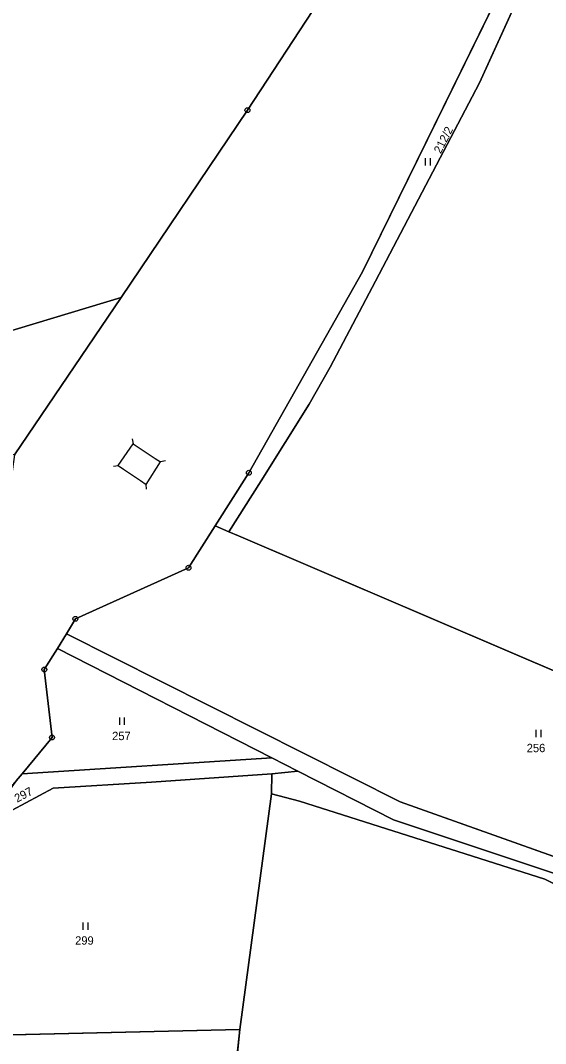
# Model space of a CAD drawing. Extents: x -689422 to -685210, y -987725 to -982160.
# Drawn here: x -686432.7 to -686325.7, y -987064.7 to -986856.4 of the extents above; entities that cross this region are included whole.
import ezdxf

# ---------------------------------------------------------------- set-up
doc = ezdxf.new("R2010")
doc.units = 0
for name, color, linetype in [('KN_Hranice_parcel', 7, 'Continuous'), ('KN_Hranice_parcel_vnitrni_kresba', 7, 'Continuous'), ('KN_Parcelni cisla', 7, 'Continuous'), ('KN_Polygon parcely', 7, 'Continuous'), ('KN_POZEMKY_ORNA PUDA', 7, 'Continuous'), ('KN_POZEMKY_OSTATNI PLOCHA', 7, 'Continuous'), ('KN_POZEMKY_TTP', 7, 'Continuous'), ('KN_POZEMKY_VODNI_PLOCHA', 7, 'Continuous'), ('KN_VYUZITI_11_vodni plocha_zamokrena plocha', 7, 'Continuous'), ('KN_VYUZITI_14_ostatni plocha_dráha', 7, 'Continuous'), ('KN_VYUZITI_17_ostatni plocha_ostatni komunikace', 7, 'Continuous'), ('KN_Značky bodu BP', 7, 'Continuous'), ('KN_Značky kultur', 7, 'Continuous')]:
    doc.layers.add(name, color=color, linetype=linetype)

msp = doc.modelspace()

# ---------------------------------------------------------------- linework, layer by layer
at = {"layer": 'KN_Hranice_parcel'}
for p, q in [((-686386.41, -986874.65), (-686371.81, -986852.38)), ((-686412.17, -986912.77), (-686386.41, -986874.65)), ((-686433.86, -986944.85), (-686412.17, -986912.77)), ((-686390.19, -986960.5), (-686392.99, -986959.3)), ((-686423.26, -986981.31), (-686425.13, -986984.29)), ((-686425.13, -986984.29), (-686381.47, -987006.54)), ((-686381.47, -987006.54), (-686432.32, -987009.81)), ((-686381.47, -987006.54), (-686376.13, -987009.26)), ((-686432.32, -987009.81), (-686433.51, -987011.26)), ((-686381.41, -987009.84), (-686381.49, -987013.89)), ((-686376.13, -987009.26), (-686381.41, -987009.84)), ((-686381.49, -987013.89), (-686387.99, -987061.9)), ((-686475.36, -987063.89), (-686387.99, -987061.9)), ((-686387.99, -987061.9), (-686391.52, -987096.84))]:
    msp.add_line(p, q, dxfattribs=at)
for points in [[(-686317.41, -986811.99), (-686334.55, -986849.71), (-686362.97, -986907.55), (-686386.12, -986948.49), (-686392.99, -986959.3)], [(-686321.02, -986828.44), (-686328.35, -986845.32), (-686339.13, -986869.1), (-686360.33, -986909.46), (-686369.53, -986927.01), (-686373.84, -986934.54), (-686383.6, -986950.14), (-686390.19, -986960.5)], [(-686505.91, -986947.47), (-686469.15, -986930), (-686412.17, -986912.77)], [(-686392.99, -986959.3), (-686398.42, -986967.84), (-686421.47, -986978.24), (-686423.26, -986981.31)], [(-686266.07, -987013.62), (-686388.26, -986961.33), (-686390.19, -986960.5)], [(-686281.29, -987046.97), (-686320.17, -987028.02), (-686355.3, -987015.5), (-686423.26, -986981.31)], [(-686425.13, -986984.29), (-686427.8, -986988.55), (-686426.23, -987002.39), (-686432.32, -987009.81)], [(-686456.99, -987046.41), (-686442.71, -987026.06), (-686434.37, -987017.22), (-686425.98, -987012.72), (-686405.99, -987011.53), (-686381.41, -987009.84)], [(-686376.13, -987009.26), (-686356.66, -987019.18), (-686321.43, -987030.92)], [(-686381.49, -987013.89), (-686375.81, -987015.35), (-686325.83, -987031.28), (-686290.35, -987048.77)]]:
    msp.add_lwpolyline(points, dxfattribs=at)
at = {"layer": 'KN_Hranice_parcel_vnitrni_kresba'}
for p, q in [((-686409.89, -986941.61), (-686409.7, -986942.59)), ((-686412.74, -986947.04), (-686409.7, -986942.59)), ((-686409.7, -986942.59), (-686408.65, -986943.29)), ((-686408.65, -986943.29), (-686405.22, -986945.56)), ((-686405.22, -986945.56), (-686404.11, -986946.29)), ((-686403.13, -986946.08), (-686404.11, -986946.29)), ((-686413.73, -986947.16), (-686412.74, -986947.04)), ((-686412.74, -986947.04), (-686411.67, -986947.76)), ((-686411.67, -986947.76), (-686408.23, -986950.08)), ((-686407.06, -986950.87), (-686404.11, -986946.29)), ((-686408.23, -986950.08), (-686407.06, -986950.87)), ((-686406.96, -986951.86), (-686407.06, -986950.87))]:
    msp.add_line(p, q, dxfattribs=at)
at = {"layer": 'KN_Polygon parcely'}
for points in [[(-686508.36, -987096.03), (-686481.22, -987061.6), (-686471.15, -987050.88), (-686433.51, -987011.26), (-686432.32, -987009.81), (-686426.23, -987002.39), (-686427.8, -986988.55), (-686425.13, -986984.29), (-686423.26, -986981.31), (-686421.47, -986978.24), (-686398.42, -986967.84), (-686392.99, -986959.3), (-686386.12, -986948.49), (-686362.97, -986907.55), (-686334.55, -986849.71), (-686317.41, -986811.99)], [(-686666.27, -986831.41), (-686673.32, -986856.41), (-686673.53, -986878.97), (-686657.04, -986918.52), (-686649.58, -986908.38), (-686637.74, -986931.17), (-686637.77, -986954.19), (-686662.38, -986982.96), (-686655.5, -986987.84), (-686651.87, -986983.58), (-686617.9, -986985.1), (-686619.46, -986983.03), (-686557.32, -986971.9), (-686505.91, -986947.47), (-686469.15, -986930), (-686412.17, -986912.77), (-686386.41, -986874.65), (-686371.81, -986852.38)], [(-686371.81, -986852.38), (-686386.41, -986874.65), (-686412.17, -986912.77), (-686433.86, -986944.85), (-686438.2, -986975.26), (-686446.86, -986992.75), (-686512, -987068.84)], [(-686320.17, -987028.02), (-686355.3, -987015.5), (-686423.26, -986981.31), (-686425.13, -986984.29), (-686381.47, -987006.54), (-686376.13, -987009.26), (-686356.66, -987019.18), (-686321.43, -987030.92)]]:
    msp.add_lwpolyline(points, dxfattribs=at)
for points in [[(-686386.12, -986948.49), (-686392.99, -986959.3), (-686390.19, -986960.5), (-686383.6, -986950.14), (-686373.84, -986934.54), (-686369.53, -986927.01), (-686360.33, -986909.46), (-686339.13, -986869.1), (-686328.35, -986845.32), (-686321.02, -986828.44), (-686314.68, -986814.02), (-686317.41, -986811.99), (-686334.55, -986849.71), (-686362.97, -986907.55)], [(-686276.46, -986963.21), (-686309.38, -986957.06), (-686258.63, -986880.97), (-686259.81, -986879.78), (-686267.39, -986864.26), (-686259.69, -986854.96), (-686314.68, -986814.02), (-686321.02, -986828.44), (-686328.35, -986845.32), (-686339.13, -986869.1), (-686360.33, -986909.46), (-686369.53, -986927.01), (-686373.84, -986934.54), (-686383.6, -986950.14), (-686390.19, -986960.5), (-686388.26, -986961.33), (-686266.07, -987013.62), (-686241.72, -986968.36)], [(-686412.17, -986912.77), (-686469.15, -986930), (-686505.91, -986947.47), (-686504.67, -986950.08), (-686451.29, -986938.63), (-686433.86, -986944.85)], [(-686388.26, -986961.33), (-686390.19, -986960.5), (-686392.99, -986959.3), (-686398.42, -986967.84), (-686421.47, -986978.24), (-686423.26, -986981.31), (-686355.3, -987015.5), (-686320.17, -987028.02), (-686281.29, -987046.97), (-686272.59, -987033.79), (-686269.9, -987020.72), (-686266.07, -987013.62)], [(-686427.8, -986988.55), (-686426.23, -987002.39), (-686432.32, -987009.81), (-686381.47, -987006.54), (-686425.13, -986984.29)], [(-686460.29, -987048.1), (-686456.99, -987046.41), (-686442.71, -987026.06), (-686434.37, -987017.22), (-686425.98, -987012.72), (-686405.99, -987011.53), (-686381.41, -987009.84), (-686376.13, -987009.26), (-686381.47, -987006.54), (-686432.32, -987009.81), (-686433.51, -987011.26)], [(-686475.36, -987063.89), (-686387.99, -987061.9), (-686381.49, -987013.89), (-686381.41, -987009.84), (-686405.99, -987011.53), (-686425.98, -987012.72), (-686434.37, -987017.22), (-686442.71, -987026.06), (-686456.99, -987046.41)], [(-686381.41, -987009.84), (-686381.49, -987013.89), (-686375.81, -987015.35), (-686325.83, -987031.28), (-686290.35, -987048.77), (-686286.57, -987047.75), (-686321.43, -987030.92), (-686356.66, -987019.18), (-686376.13, -987009.26)], [(-686324.19, -987147.76), (-686323.46, -987140.67), (-686321.18, -987118.05), (-686294.87, -987050.2), (-686290.35, -987048.77), (-686325.83, -987031.28), (-686375.81, -987015.35), (-686381.49, -987013.89), (-686387.99, -987061.9), (-686391.52, -987096.84), (-686396.13, -987140.43)], [(-686505.61, -987095.9), (-686391.52, -987096.84), (-686387.99, -987061.9), (-686475.36, -987063.89), (-686488.8, -987073.41)]]:
    msp.add_lwpolyline(points, close=True, dxfattribs=at)
at = {"layer": 'KN_POZEMKY_ORNA PUDA'}
for p, q in [((-686371.81, -986852.38), (-686386.41, -986874.65)), ((-686386.41, -986874.65), (-686412.17, -986912.77)), ((-686412.17, -986912.77), (-686469.15, -986930))]:
    msp.add_line(p, q, dxfattribs=at)
at = {"layer": 'KN_POZEMKY_OSTATNI PLOCHA'}
for p, q in [((-686334.55, -986849.71), (-686362.97, -986907.55)), ((-686386.41, -986874.65), (-686371.81, -986852.38)), ((-686412.17, -986912.77), (-686386.41, -986874.65)), ((-686362.97, -986907.55), (-686386.12, -986948.49)), ((-686433.86, -986944.85), (-686412.17, -986912.77)), ((-686386.12, -986948.49), (-686392.99, -986959.3)), ((-686392.99, -986959.3), (-686398.42, -986967.84)), ((-686398.42, -986967.84), (-686421.47, -986978.24)), ((-686421.47, -986978.24), (-686423.26, -986981.31)), ((-686423.26, -986981.31), (-686425.13, -986984.29)), ((-686425.13, -986984.29), (-686423.26, -986981.31)), ((-686423.26, -986981.31), (-686355.3, -987015.5)), ((-686425.13, -986984.29), (-686427.8, -986988.55)), ((-686381.47, -987006.54), (-686425.13, -986984.29)), ((-686427.8, -986988.55), (-686426.23, -987002.39)), ((-686426.23, -987002.39), (-686432.32, -987009.81)), ((-686432.32, -987009.81), (-686381.47, -987006.54)), ((-686376.13, -987009.26), (-686381.47, -987006.54)), ((-686381.47, -987006.54), (-686376.13, -987009.26)), ((-686432.32, -987009.81), (-686433.51, -987011.26)), ((-686433.51, -987011.26), (-686432.32, -987009.81)), ((-686381.41, -987009.84), (-686405.99, -987011.53)), ((-686376.13, -987009.26), (-686381.41, -987009.84)), ((-686356.66, -987019.18), (-686376.13, -987009.26)), ((-686425.98, -987012.72), (-686434.37, -987017.22)), ((-686405.99, -987011.53), (-686425.98, -987012.72)), ((-686355.3, -987015.5), (-686320.17, -987028.02)), ((-686321.43, -987030.92), (-686356.66, -987019.18))]:
    msp.add_line(p, q, dxfattribs=at)
at = {"layer": 'KN_POZEMKY_TTP'}
for p, q in [((-686339.13, -986869.1), (-686328.35, -986845.32)), ((-686328.35, -986845.32), (-686339.13, -986869.1)), ((-686362.97, -986907.55), (-686334.55, -986849.71)), ((-686360.33, -986909.46), (-686339.13, -986869.1)), ((-686339.13, -986869.1), (-686360.33, -986909.46)), ((-686386.12, -986948.49), (-686362.97, -986907.55)), ((-686369.53, -986927.01), (-686360.33, -986909.46)), ((-686360.33, -986909.46), (-686369.53, -986927.01)), ((-686373.84, -986934.54), (-686369.53, -986927.01)), ((-686369.53, -986927.01), (-686373.84, -986934.54)), ((-686383.6, -986950.14), (-686373.84, -986934.54)), ((-686373.84, -986934.54), (-686383.6, -986950.14)), ((-686392.99, -986959.3), (-686386.12, -986948.49)), ((-686390.19, -986960.5), (-686383.6, -986950.14)), ((-686383.6, -986950.14), (-686390.19, -986960.5)), ((-686398.42, -986967.84), (-686392.99, -986959.3)), ((-686390.19, -986960.5), (-686392.99, -986959.3)), ((-686392.99, -986959.3), (-686390.19, -986960.5)), ((-686388.26, -986961.33), (-686390.19, -986960.5)), ((-686390.19, -986960.5), (-686388.26, -986961.33)), ((-686266.07, -987013.62), (-686388.26, -986961.33)), ((-686388.26, -986961.33), (-686266.07, -987013.62)), ((-686421.47, -986978.24), (-686398.42, -986967.84)), ((-686423.26, -986981.31), (-686421.47, -986978.24)), ((-686355.3, -987015.5), (-686423.26, -986981.31)), ((-686427.8, -986988.55), (-686425.13, -986984.29)), ((-686425.13, -986984.29), (-686381.47, -987006.54)), ((-686426.23, -987002.39), (-686427.8, -986988.55)), ((-686432.32, -987009.81), (-686426.23, -987002.39)), ((-686381.47, -987006.54), (-686432.32, -987009.81)), ((-686405.99, -987011.53), (-686381.41, -987009.84)), ((-686381.49, -987013.89), (-686381.41, -987009.84)), ((-686381.41, -987009.84), (-686381.49, -987013.89)), ((-686381.41, -987009.84), (-686376.13, -987009.26)), ((-686376.13, -987009.26), (-686356.66, -987019.18)), ((-686434.37, -987017.22), (-686425.98, -987012.72)), ((-686425.98, -987012.72), (-686405.99, -987011.53)), ((-686387.99, -987061.9), (-686381.49, -987013.89)), ((-686381.49, -987013.89), (-686387.99, -987061.9)), ((-686381.49, -987013.89), (-686375.81, -987015.35)), ((-686375.81, -987015.35), (-686381.49, -987013.89)), ((-686375.81, -987015.35), (-686325.83, -987031.28)), ((-686325.83, -987031.28), (-686375.81, -987015.35)), ((-686320.17, -987028.02), (-686355.3, -987015.5)), ((-686356.66, -987019.18), (-686321.43, -987030.92)), ((-686325.83, -987031.28), (-686290.35, -987048.77)), ((-686290.35, -987048.77), (-686325.83, -987031.28)), ((-686387.99, -987061.9), (-686475.36, -987063.89)), ((-686475.36, -987063.89), (-686387.99, -987061.9)), ((-686391.52, -987096.84), (-686387.99, -987061.9)), ((-686387.99, -987061.9), (-686391.52, -987096.84))]:
    msp.add_line(p, q, dxfattribs=at)
at = {"layer": 'KN_POZEMKY_VODNI_PLOCHA'}
for p, q in [((-686469.15, -986930), (-686412.17, -986912.77)), ((-686412.17, -986912.77), (-686433.86, -986944.85))]:
    msp.add_line(p, q, dxfattribs=at)
at = {"layer": 'KN_VYUZITI_11_vodni plocha_zamokrena plocha'}
for p, q in [((-686469.15, -986930), (-686412.17, -986912.77)), ((-686412.17, -986912.77), (-686433.86, -986944.85))]:
    msp.add_line(p, q, dxfattribs=at)
at = {"layer": 'KN_VYUZITI_14_ostatni plocha_dráha'}
for p, q in [((-686334.55, -986849.71), (-686362.97, -986907.55)), ((-686386.41, -986874.65), (-686371.81, -986852.38)), ((-686412.17, -986912.77), (-686386.41, -986874.65)), ((-686362.97, -986907.55), (-686386.12, -986948.49)), ((-686433.86, -986944.85), (-686412.17, -986912.77)), ((-686386.12, -986948.49), (-686392.99, -986959.3)), ((-686392.99, -986959.3), (-686398.42, -986967.84)), ((-686398.42, -986967.84), (-686421.47, -986978.24)), ((-686421.47, -986978.24), (-686423.26, -986981.31)), ((-686423.26, -986981.31), (-686425.13, -986984.29)), ((-686425.13, -986984.29), (-686427.8, -986988.55)), ((-686427.8, -986988.55), (-686426.23, -987002.39)), ((-686426.23, -987002.39), (-686432.32, -987009.81)), ((-686432.32, -987009.81), (-686433.51, -987011.26))]:
    msp.add_line(p, q, dxfattribs=at)
at = {"layer": 'KN_VYUZITI_17_ostatni plocha_ostatni komunikace'}
for p, q in [((-686425.13, -986984.29), (-686423.26, -986981.31)), ((-686423.26, -986981.31), (-686355.3, -987015.5)), ((-686381.47, -987006.54), (-686425.13, -986984.29)), ((-686432.32, -987009.81), (-686381.47, -987006.54)), ((-686376.13, -987009.26), (-686381.47, -987006.54)), ((-686381.47, -987006.54), (-686376.13, -987009.26)), ((-686433.51, -987011.26), (-686432.32, -987009.81)), ((-686381.41, -987009.84), (-686405.99, -987011.53)), ((-686376.13, -987009.26), (-686381.41, -987009.84)), ((-686356.66, -987019.18), (-686376.13, -987009.26)), ((-686425.98, -987012.72), (-686434.37, -987017.22)), ((-686405.99, -987011.53), (-686425.98, -987012.72)), ((-686355.3, -987015.5), (-686320.17, -987028.02)), ((-686321.43, -987030.92), (-686356.66, -987019.18))]:
    msp.add_line(p, q, dxfattribs=at)
at = {"layer": 'KN_Značky bodu BP'}
for centre, radius in [((-686386.41, -986874.65), 0.5), ((-686386.41, -986874.65), 0.0303), ((-686386.12, -986948.49), 0.5), ((-686386.12, -986948.49), 0.0303), ((-686398.42, -986967.84), 0.5), ((-686398.42, -986967.84), 0.0303), ((-686421.47, -986978.24), 0.5), ((-686421.47, -986978.24), 0.0303), ((-686427.8, -986988.55), 0.5), ((-686427.8, -986988.55), 0.0303), ((-686426.23, -987002.39), 0.5), ((-686426.23, -987002.39), 0.0303)]:
    msp.add_circle(centre, radius, dxfattribs=at)
at = {"layer": 'KN_Značky kultur'}
for p, q in [((-686350.13, -986885.94), (-686350.13, -986884.44)), ((-686349.13, -986885.94), (-686349.13, -986884.44)), ((-686412.44, -986999.83), (-686412.44, -986998.33)), ((-686411.44, -986999.83), (-686411.44, -986998.33)), ((-686327.55, -987002.35), (-686327.55, -987000.85)), ((-686326.55, -987002.35), (-686326.55, -987000.85)), ((-686419.9, -987041.56), (-686419.9, -987040.06)), ((-686418.9, -987041.56), (-686418.9, -987040.06))]:
    msp.add_line(p, q, dxfattribs=at)

# ---------------------------------------------------------------- texts
at = {"layer": 'KN_Parcelni cisla'}
for s, rotation, p in [('212/2', 63, (-686347.03, -986883.61)), ('297', 28, (-686433.34, -987015.7))]:
    msp.add_text(s, height=1.7, rotation=rotation, dxfattribs=at).set_placement(p)
for s, p in [('257', (-686413.99, -987002.94)), ('256', (-686329.51, -987005.4)), ('299', (-686421.53, -987044.6))]:
    msp.add_text(s, height=1.7, dxfattribs=at).set_placement(p)

doc.saveas('drawing.dxf')
